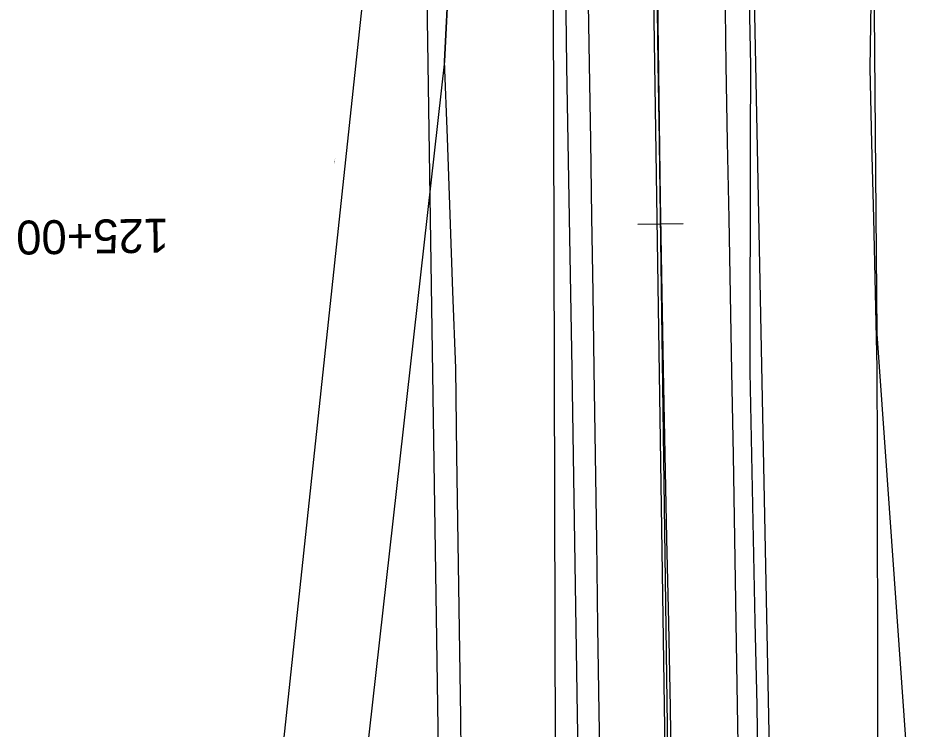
# Model space of a CAD drawing. Extents: x 1674300 to 1677920, y 225056 to 231852.
# Drawn here: x 1677252.7 to 1677410.1, y 229688.4 to 229814.1 of the extents above; entities that cross this region are included whole.
import ezdxf

# ---------------------------------------------------------------- set-up
doc = ezdxf.new("R2010")
doc.units = 0
for name, color, linetype in [('Default', 7, 'Continuous'), ('R_Annotation', 7, 'Continuous'), ('R_Axis', 7, 'Continuous'), ('R_Horz Alg', 7, 'Continuous'), ('R_Horz Alg Annot', 7, 'Continuous'), ('R_Proposed Const Limits_Cut', 7, 'Continuous'), ('R_Proposed Const Limits_Fill', 7, 'Continuous'), ('R_ROW', 7, 'Continuous'), ('S_DITCHLINE', 7, 'Continuous'), ('S_EDGE_PAVEMENT', 7, 'Continuous'), ('S_EXIST_ROW', 7, 'Continuous'), ('S_EXISTING_ALIGNMENT', 7, 'Continuous'), ('S_PAVEMENT_CROWN', 7, 'Continuous'), ('S_SHOULDER', 7, 'Continuous')]:
    doc.layers.add(name, color=color, linetype=linetype)

msp = doc.modelspace()

# ---------------------------------------------------------------- linework, layer by layer
at = {"layer": 'Default'}
msp.add_line((1677360.58, 230177.65), (1677366.2, 229777.69), dxfattribs=at)
at = {"layer": 'R_Axis'}
for p, q in [((1677346.67, 230027.44), (1677347.61, 229677.42)), ((1677385.61, 229677.95), (1677378.51, 230027.89))]:
    msp.add_line(p, q, dxfattribs=at)
at = {"layer": 'R_Horz Alg'}
msp.add_line((1677377.01, 229008.91), (1677360.58, 230177.65), dxfattribs=at)
at = {"layer": 'R_Horz Alg Annot'}
msp.add_lwpolyline([(1677362.2, 229777.64), (1677370.2, 229777.75)], dxfattribs=at)
at = {"layer": 'R_Proposed Const Limits_Cut'}
msp.add_lwpolyline([(1677331.55, 230027.23), (1677331.85, 229955.95), (1677331.75, 229909.6), (1677330.88, 229862.77), (1677328.06, 229806.45), (1677313.48, 229676.94)], dxfattribs=at)
at = {"layer": 'R_Proposed Const Limits_Fill'}
msp.add_lwpolyline([(1677410.12, 229678.3), (1677404.47, 229758.23), (1677402.22, 230028.22), (1677378.51, 230027.89)], dxfattribs=at)
at = {"layer": 'R_ROW'}
msp.add_line((1677293.32, 229626.65), (1677323.6, 229911.16), dxfattribs=at)
at = {"layer": 'S_DITCHLINE'}
for points in [[(1677404.65, 229678.97), (1677404.58, 229692.77), (1677404.56, 229707.64), (1677404.53, 229722.52), (1677404.5, 229737.39), (1677404.48, 229752.27), (1677404.17, 229765.49), (1677403.85, 229778.72), (1677403.54, 229791.95), (1677403.23, 229805.18), (1677403.49, 229820.68), (1677403.74, 229836.18), (1677404, 229851.68), (1677404.26, 229867.18), (1677403.93, 229879.75), (1677403.6, 229892.32), (1677403.27, 229904.89), (1677402.94, 229917.46), (1677403.01, 229931.27), (1677403.07, 229945.08)], [(1677331.06, 229677.4), (1677330.9, 229690.57), (1677330.68, 229705.98), (1677330.46, 229721.38), (1677330.24, 229736.79), (1677330.02, 229752.2), (1677329.53, 229765.76), (1677329.04, 229779.32), (1677328.55, 229792.89), (1677328.06, 229806.45), (1677328.76, 229820.53), (1677329.47, 229834.61), (1677330.17, 229848.69), (1677330.88, 229862.77), (1677331.13, 229876.15), (1677331.37, 229889.53), (1677331.62, 229902.91), (1677331.87, 229916.29), (1677331.86, 229929.51), (1677331.85, 229942.73)]]:
    msp.add_lwpolyline(points, dxfattribs=at)
at = {"layer": 'S_EDGE_PAVEMENT'}
for points in [[(1677380.02, 229678.98), (1677379.81, 229692.57), (1677379.56, 229707.33), (1677379.31, 229722.08), (1677379.07, 229736.83), (1677378.82, 229751.59), (1677378.56, 229765.13), (1677378.3, 229778.66), (1677378.04, 229792.2), (1677377.78, 229805.74), (1677377.62, 229820.28), (1677377.45, 229834.83), (1677377.29, 229849.38), (1677377.12, 229863.92), (1677376.94, 229877.3), (1677376.76, 229890.67), (1677376.58, 229904.05), (1677376.4, 229917.43), (1677376.18, 229930.95), (1677375.96, 229944.47)], [(1677355.57, 229678.21), (1677355.36, 229691.32), (1677355.14, 229706.5), (1677354.93, 229721.67), (1677354.71, 229736.85), (1677354.49, 229752.02), (1677354.28, 229765.49), (1677354.07, 229778.96), (1677353.86, 229792.42), (1677353.65, 229805.89), (1677353.42, 229820.19), (1677353.19, 229834.49), (1677352.96, 229848.79), (1677352.73, 229863.09), (1677352.52, 229876.59), (1677352.3, 229890.09), (1677352.09, 229903.59), (1677351.87, 229917.09), (1677351.68, 229930.08), (1677351.49, 229943.07)]]:
    msp.add_lwpolyline(points, dxfattribs=at)
at = {"layer": 'S_EXIST_ROW'}
msp.add_line((1677337.07, 229010.49), (1677299.88, 231497.46), dxfattribs=at)
at = {"layer": 'S_EXISTING_ALIGNMENT'}
msp.add_line((1677375.22, 229134.43), (1677343.44, 231259.98), dxfattribs=at)
at = {"layer": 'S_PAVEMENT_CROWN'}
msp.add_lwpolyline([(1677368.12, 229678.74), (1677367.96, 229692.25), (1677367.65, 229707.17), (1677367.34, 229722.09), (1677367.03, 229737.01), (1677366.71, 229751.93), (1677366.48, 229765.43), (1677366.24, 229778.94), (1677366, 229792.45), (1677365.77, 229805.96), (1677365.61, 229820.3), (1677365.44, 229834.63), (1677365.28, 229848.97), (1677365.12, 229863.3), (1677364.85, 229876.81), (1677364.57, 229890.32), (1677364.3, 229903.83), (1677364.03, 229917.33), (1677363.9, 229930.66), (1677363.77, 229943.99)], dxfattribs=at)
at = {"layer": 'S_SHOULDER'}
for points in [[(1677383.46, 229679.08), (1677383.25, 229692.66), (1677382.94, 229707.39), (1677382.63, 229722.11), (1677382.33, 229736.83), (1677382.02, 229751.55), (1677382.05, 229765.07), (1677382.08, 229778.59), (1677382.11, 229792.11), (1677382.14, 229805.64), (1677381.83, 229820.25), (1677381.52, 229834.86), (1677381.21, 229849.48), (1677380.9, 229864.09), (1677380.69, 229877.47), (1677380.49, 229890.84), (1677380.29, 229904.22), (1677380.09, 229917.59), (1677379.89, 229931.11), (1677379.69, 229944.63)], [(1677351.74, 229677.91), (1677351.54, 229690.95), (1677351.3, 229706.22), (1677351.06, 229721.48), (1677350.82, 229736.74), (1677350.58, 229752.01), (1677350.35, 229765.39), (1677350.12, 229778.77), (1677349.89, 229792.16), (1677349.65, 229805.54), (1677349.5, 229819.92), (1677349.34, 229834.31), (1677349.19, 229848.69), (1677349.04, 229863.07), (1677348.81, 229876.61), (1677348.59, 229890.14), (1677348.37, 229903.68), (1677348.14, 229917.22), (1677347.94, 229930.05), (1677347.74, 229942.88)]]:
    msp.add_lwpolyline(points, dxfattribs=at)

# ---------------------------------------------------------------- texts
at = {"layer": 'R_Annotation'}
msp.add_text('PROP. R/W', height=0.12, rotation=82.942, dxfattribs=at).set_placement((1677308.68, 229788.38))
at = {"layer": 'R_Horz Alg Annot'}
msp.add_text('125+00', height=6, rotation=180.8056, dxfattribs=at).set_placement((1677279.33, 229778.63))

doc.saveas('drawing.dxf')
